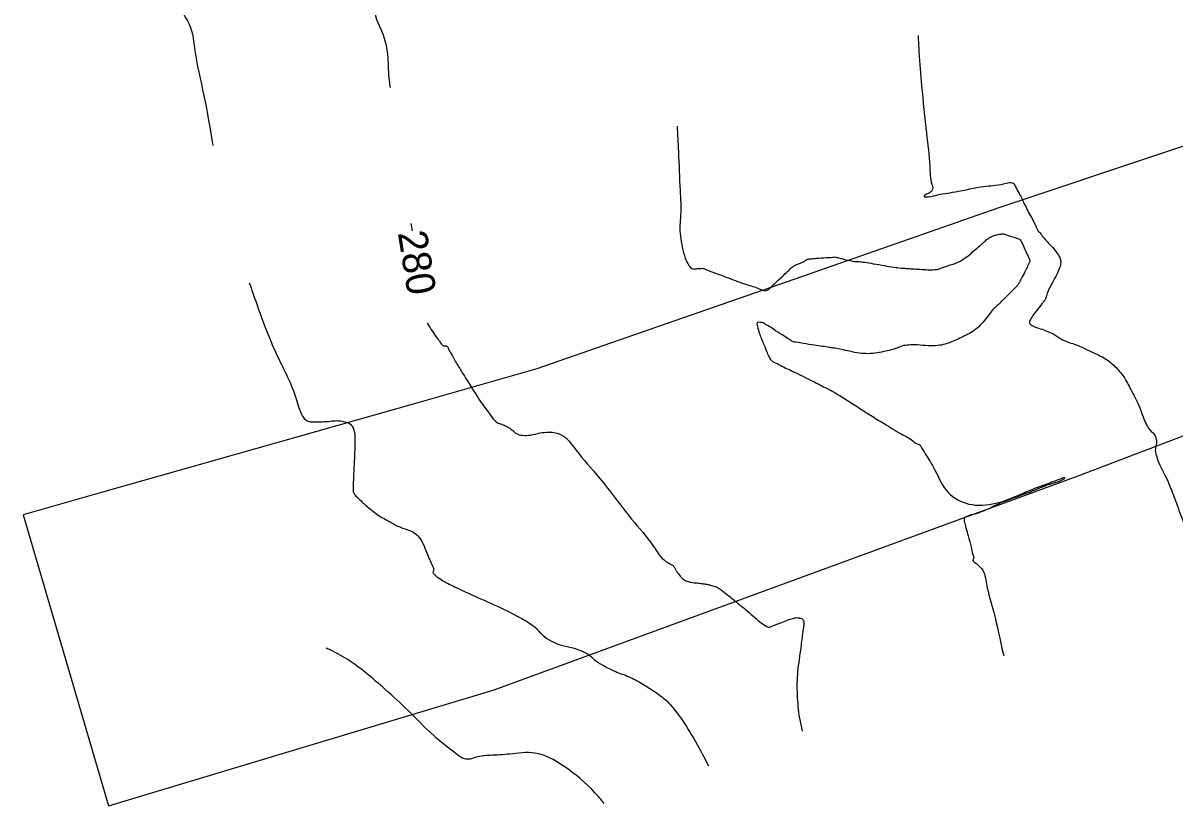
# Model space of a CAD drawing. Extents: x -478645 to -472650, y -1118147 to -1113892.
# Drawn here: x -476249.6 to -476090.4, y -1115350.3 to -1115242.1 of the extents above; entities that cross this region are included whole.
import ezdxf

# ---------------------------------------------------------------- set-up
doc = ezdxf.new("R2010")
doc.units = 0
for name, color, linetype in [('ObPÚ', 7, 'Continuous'), ('Vrstevnice_hlavni', 7, 'Continuous'), ('Vrstevnice_popis', 7, 'Continuous'), ('Vrstevnice_vedlejsi', 7, 'Continuous')]:
    doc.layers.add(name, color=color, linetype=linetype)

msp = doc.modelspace()

# ---------------------------------------------------------------- linework, layer by layer
at = {"layer": 'ObPÚ'}
msp.add_lwpolyline([(-476068.7, -1115252.31), (-476114.88, -1115267.73), (-476138.618, -1115276.003), (-476141.91, -1115277.15), (-476168.45, -1115286.39), (-476178.6, -1115289.93), (-476195.38, -1115294.7), (-476223.04, -1115302.55), (-476238.65, -1115306.98), (-476249.64, -1115310.1), (-476237.84, -1115350.34), (-476184.5, -1115334.29), (-476103.79, -1115304.74), (-476065.34, -1115290.09)], dxfattribs=at)
at = {"layer": 'Vrstevnice_hlavni'}
msp.add_line((-476196.015, -1115269.846), (-476195.861, -1115270.85), dxfattribs=at)
for points in [[(-476040.384, -1115118.458), (-476041.47, -1115119.89), (-476042.412, -1115121.448), (-476043.751, -1115123.849), (-476045.488, -1115127.091), (-476046.696, -1115129.513), (-476047.375, -1115131.113), (-476047.526, -1115131.894), (-476048.073, -1115133.254), (-476049.018, -1115135.194), (-476050.36, -1115137.713), (-476052.374, -1115140.598), (-476055.061, -1115143.847), (-476058.422, -1115147.462), (-476060.881, -1115150.366), (-476062.441, -1115152.562), (-476063.1, -1115154.048), (-476064.028, -1115155.224), (-476065.225, -1115156.09), (-476066.691, -1115156.645), (-476068.203, -1115157.501), (-476069.761, -1115158.657), (-476071.364, -1115160.113), (-476073.585, -1115161.644), (-476076.424, -1115163.251), (-476079.881, -1115164.932), (-476082.243, -1115166.084), (-476083.511, -1115166.709), (-476083.684, -1115166.806), (-476083.884, -1115166.906), (-476084.109, -1115167.009), (-476084.361, -1115167.115), (-476085.47, -1115168.111), (-476087.436, -1115169.998), (-476090.259, -1115172.776), (-476094.056, -1115175.649), (-476098.828, -1115178.618), (-476104.575, -1115181.683), (-476109.757, -1115183.949), (-476114.374, -1115185.417), (-476118.425, -1115186.088), (-476122.042, -1115187.328), (-476125.226, -1115189.137), (-476127.977, -1115191.516), (-476131.019, -1115193.792), (-476134.353, -1115195.963), (-476137.979, -1115198.031), (-476141.984, -1115199.581), (-476146.368, -1115200.612), (-476151.132, -1115201.124), (-476157.864, -1115204.368), (-476166.565, -1115210.343), (-476177.234, -1115219.049), (-476184.652, -1115224.996), (-476188.817, -1115228.184), (-476189.731, -1115228.613), (-476190.168, -1115228.886), (-476190.128, -1115229.002), (-476189.61, -1115228.963), (-476189.269, -1115228.999), (-476189.104, -1115229.11), (-476189.116, -1115229.298), (-476189.143, -1115229.675), (-476189.187, -1115230.241), (-476189.246, -1115230.996), (-476189.162, -1115231.612), (-476188.933, -1115232.089), (-476188.56, -1115232.427), (-476188.448, -1115232.74), (-476188.595, -1115233.026), (-476189.004, -1115233.287), (-476189.464, -1115233.625), (-476189.976, -1115234.04), (-476190.541, -1115234.531), (-476191.953, -1115235.382), (-476194.211, -1115236.59), (-476197.317, -1115238.157), (-476199.41, -1115239.209), (-476200.49, -1115239.748), (-476200.557, -1115239.773), (-476200.072, -1115243.239), (-476199.036, -1115250.148), (-476198.895, -1115251.068)], [(-476193.757, -1115283.639), (-476192.399, -1115285.697), (-476191.876, -1115286.389), (-476191.509, -1115286.744), (-476191.298, -1115286.761), (-476191.153, -1115286.774), (-476191.075, -1115286.783), (-476191.063, -1115286.789), (-476190.853, -1115287.151), (-476190.446, -1115287.871), (-476189.842, -1115288.948), (-476188.923, -1115290.467), (-476187.688, -1115292.429), (-476186.137, -1115294.833), (-476184.891, -1115296.504), (-476183.948, -1115297.443), (-476183.309, -1115297.648), (-476182.68, -1115297.954), (-476182.06, -1115298.362), (-476181.45, -1115298.872), (-476180.595, -1115299.114), (-476179.497, -1115299.088), (-476178.155, -1115298.795), (-476176.997, -1115298.69), (-476176.025, -1115298.773), (-476175.238, -1115299.045), (-476173.224, -1115301.122), (-476169.984, -1115305.003), (-476165.518, -1115310.689), (-476162.449, -1115314.535), (-476160.779, -1115316.54), (-476160.507, -1115316.704), (-476160.264, -1115316.845), (-476160.048, -1115316.962), (-476159.86, -1115317.056), (-476159.707, -1115317.19), (-476159.59, -1115317.365), (-476159.508, -1115317.58), (-476159.311, -1115317.896), (-476158.998, -1115318.315), (-476158.57, -1115318.834), (-476158.007, -1115319.207), (-476157.308, -1115319.433), (-476156.473, -1115319.513), (-476155.76, -1115319.601), (-476155.169, -1115319.698), (-476154.699, -1115319.804), (-476154.303, -1115319.906), (-476153.978, -1115320.004), (-476153.727, -1115320.098), (-476153.145, -1115320.495), (-476152.232, -1115321.193), (-476150.988, -1115322.193), (-476149.831, -1115323.145), (-476148.761, -1115324.046), (-476147.778, -1115324.899), (-476147.017, -1115325.426), (-476146.478, -1115325.629), (-476146.16, -1115325.507), (-476145.635, -1115325.303), (-476144.904, -1115325.017), (-476143.967, -1115324.649), (-476143.233, -1115324.414), (-476142.702, -1115324.312), (-476142.375, -1115324.342), (-476142.123, -1115324.398), (-476141.945, -1115324.481), (-476141.842, -1115324.59), (-476141.767, -1115324.715), (-476141.722, -1115324.858), (-476141.705, -1115325.018), (-476141.842, -1115326.221), (-476142.131, -1115328.466), (-476142.574, -1115331.753), (-476142.636, -1115334.999), (-476142.32, -1115338.203), (-476141.962, -1115339.984)]]:
    msp.add_spline(points, degree=3, dxfattribs=at)
at = {"layer": 'Vrstevnice_vedlejsi'}
for points in [[(-476075.436, -1115157.873), (-476077.562, -1115158.907), (-476079.639, -1115159.964), (-476081.666, -1115161.045), (-476083.644, -1115162.149), (-476085.921, -1115163.289), (-476088.498, -1115164.465), (-476091.373, -1115165.676), (-476093.656, -1115166.843), (-476095.346, -1115167.967), (-476096.444, -1115169.047), (-476097.921, -1115170.165), (-476099.777, -1115171.319), (-476102.012, -1115172.511), (-476105.743, -1115173.677), (-476110.97, -1115174.816), (-476117.692, -1115175.928), (-476122.561, -1115177.005), (-476125.576, -1115178.045), (-476126.738, -1115179.05), (-476129.738, -1115180.989), (-476134.578, -1115183.864), (-476141.257, -1115187.673), (-476147.035, -1115190.356), (-476151.912, -1115191.911), (-476155.888, -1115192.338), (-476158.789, -1115192.754), (-476160.614, -1115193.159), (-476161.364, -1115193.552), (-476162.517, -1115193.939), (-476164.073, -1115194.319), (-476166.032, -1115194.693), (-476167.609, -1115195.158), (-476168.804, -1115195.715), (-476169.616, -1115196.364), (-476170.816, -1115197.116), (-476172.405, -1115197.973), (-476174.383, -1115198.934), (-476179.537, -1115202.555), (-476187.868, -1115208.836), (-476199.377, -1115217.776), (-476207.75, -1115223.932), (-476212.989, -1115227.302), (-476215.093, -1115227.888), (-476217.31, -1115229.046), (-476219.639, -1115230.776), (-476222.081, -1115233.079), (-476224.102, -1115235.091), (-476225.704, -1115236.812), (-476226.884, -1115238.243), (-476227.475, -1115239.561), (-476227.475, -1115240.767), (-476226.885, -1115241.861), (-476225.939, -1115245.662), (-476224.639, -1115252.17), (-476223.41, -1115259.087)], [(-476125.929, -1115243.884), (-476125.807, -1115246.158), (-476125.427, -1115250.782), (-476124.774, -1115257.383), (-476124.301, -1115261.931), (-476124.008, -1115264.426), (-476123.894, -1115264.868), (-476123.981, -1115265.246), (-476124.269, -1115265.56), (-476124.757, -1115265.811), (-476125.029, -1115265.996), (-476125.083, -1115266.115), (-476124.92, -1115266.169), (-476123.491, -1115265.956), (-476120.797, -1115265.476), (-476116.836, -1115264.728), (-476114.123, -1115264.363), (-476112.657, -1115264.382), (-476112.438, -1115264.783), (-476111.966, -1115265.692), (-476111.241, -1115267.111), (-476110.263, -1115269.038), (-476109.58, -1115270.343), (-476109.193, -1115271.027), (-476109.102, -1115271.089), (-476109.038, -1115271.136), (-476109.003, -1115271.169), (-476108.995, -1115271.186), (-476108.962, -1115271.248), (-476108.904, -1115271.357), (-476108.821, -1115271.512), (-476108.502, -1115271.894), (-476107.946, -1115272.505), (-476107.155, -1115273.343), (-476106.601, -1115274.081), (-476106.285, -1115274.719), (-476106.206, -1115275.258), (-476106.359, -1115275.986), (-476106.744, -1115276.905)], [(-476159.242, -1115256.374), (-476159.054, -1115259.908), (-476158.82, -1115265.295), (-476158.75, -1115268.706), (-476158.845, -1115270.139), (-476158.769, -1115271.604), (-476158.523, -1115273.101), (-476158.106, -1115274.629), (-476157.613, -1115275.635), (-476157.044, -1115276.119), (-476156.398, -1115276.081), (-476155.961, -1115276.055), (-476155.733, -1115276.04), (-476155.713, -1115276.036), (-476155.581, -1115276.081), (-476155.338, -1115276.173), (-476154.983, -1115276.314), (-476153.911, -1115276.714), (-476152.122, -1115277.373), (-476149.617, -1115278.29), (-476147.877, -1115278.87), (-476146.903, -1115279.111), (-476146.694, -1115279.015), (-476146.533, -1115278.92), (-476146.42, -1115278.827), (-476146.354, -1115278.736), (-476146.034, -1115278.42), (-476145.458, -1115277.878), (-476144.627, -1115277.111), (-476144.009, -1115276.53), (-476143.606, -1115276.135), (-476143.416, -1115275.928), (-476143.115, -1115275.721), (-476142.7, -1115275.515), (-476142.174, -1115275.31), (-476141.777, -1115275.132), (-476141.512, -1115274.98), (-476141.376, -1115274.855), (-476140.853, -1115274.744), (-476139.943, -1115274.647), (-476138.645, -1115274.565), (-476137.773, -1115274.512), (-476137.326, -1115274.488), (-476137.304, -1115274.493), (-476137.022, -1115274.564), (-476136.479, -1115274.699), (-476135.676, -1115274.9), (-476135.01, -1115275.037), (-476134.48, -1115275.109), (-476134.087, -1115275.117), (-476133.301, -1115275.213), (-476132.123, -1115275.399), (-476130.553, -1115275.673), (-476129.267, -1115275.873), (-476128.264, -1115275.998), (-476127.545, -1115276.049), (-476126.691, -1115276.105), (-476125.702, -1115276.169), (-476124.578, -1115276.238), (-476123.673, -1115276.222), (-476122.988, -1115276.122), (-476122.522, -1115275.938), (-476121.968, -1115275.735), (-476121.325, -1115275.516), (-476120.594, -1115275.279), (-476119.818, -1115274.872), (-476118.996, -1115274.295), (-476118.13, -1115273.548), (-476117.407, -1115272.922), (-476116.827, -1115272.417), (-476116.391, -1115272.033), (-476115.924, -1115271.733), (-476115.425, -1115271.516), (-476114.896, -1115271.383), (-476114.504, -1115271.301), (-476114.247, -1115271.269), (-476114.127, -1115271.287), (-476113.822, -1115271.374), (-476113.331, -1115271.529), (-476112.656, -1115271.752), (-476112.177, -1115271.921), (-476111.894, -1115272.035), (-476111.807, -1115272.094), (-476111.623, -1115272.416), (-476111.341, -1115273)], [(-476111.341, -1115273), (-476110.962, -1115273.848), (-476110.694, -1115274.441), (-476110.537, -1115274.78), (-476110.491, -1115274.865), (-476110.47, -1115274.959), (-476110.475, -1115275.062), (-476110.506, -1115275.174), (-476110.69, -1115275.573), (-476111.03, -1115276.26), (-476111.524, -1115277.233), (-476111.877, -1115277.912), (-476112.088, -1115278.296), (-476112.158, -1115278.386), (-476112.514, -1115278.752), (-476113.156, -1115279.397), (-476114.085, -1115280.319), (-476114.761, -1115280.979), (-476115.186, -1115281.379), (-476115.36, -1115281.517), (-476115.713, -1115281.919), (-476116.247, -1115282.585), (-476116.962, -1115283.514), (-476117.741, -1115284.291), (-476118.584, -1115284.915), (-476119.493, -1115285.387), (-476120.392, -1115285.812), (-476121.284, -1115286.191), (-476122.167, -1115286.523), (-476123.251, -1115286.707), (-476124.536, -1115286.741), (-476126.022, -1115286.628), (-476127.231, -1115286.643), (-476128.162, -1115286.786), (-476128.816, -1115287.059), (-476129.654, -1115287.316), (-476130.678, -1115287.555), (-476131.887, -1115287.779), (-476133.124, -1115287.833), (-476134.388, -1115287.719), (-476135.68, -1115287.435), (-476136.751, -1115287.215), (-476137.602, -1115287.058), (-476138.232, -1115286.963), (-476139.134, -1115286.827), (-476140.308, -1115286.649), (-476141.754, -1115286.429), (-476142.752, -1115286.26), (-476143.303, -1115286.142), (-476143.406, -1115286.075), (-476143.876, -1115285.775), (-476144.711, -1115285.24), (-476145.912, -1115284.47), (-476146.719, -1115283.95), (-476147.131, -1115283.678), (-476147.149, -1115283.654), (-476147.194, -1115283.626), (-476147.267, -1115283.594), (-476147.366, -1115283.557), (-476147.542, -1115283.533), (-476147.795, -1115283.522), (-476148.124, -1115283.524), (-476148.141, -1115284.035), (-476147.848, -1115285.056), (-476147.243, -1115286.586), (-476146.785, -1115287.691), (-476146.474, -1115288.372), (-476146.31, -1115288.628), (-476146.156, -1115288.817), (-476146.012, -1115288.938), (-476145.878, -1115288.992), (-476144.948, -1115289.442), (-476143.224, -1115290.289), (-476140.705, -1115291.532), (-476138.75, -1115292.524), (-476137.361, -1115293.265), (-476136.537, -1115293.756), (-476135.685, -1115294.285), (-476134.806, -1115294.853), (-476133.899, -1115295.46), (-476132.503, -1115296.342), (-476130.618, -1115297.498), (-476128.243, -1115298.929), (-476126.641, -1115299.885), (-476125.811, -1115300.366), (-476125.755, -1115300.372), (-476125.7, -1115300.405), (-476125.646, -1115300.464), (-476125.594, -1115300.551), (-476124.922, -1115301.679), (-476123.631, -1115303.848), (-476121.721, -1115307.059), (-476118.902, -1115308.612), (-476115.176, -1115308.508), (-476110.541, -1115306.747), (-476107.432, -1115305.567), (-476105.848, -1115304.97)], [(-476218.376, -1115278.038), (-476217.875, -1115279.456), (-476214.425, -1115288.313), (-476211.835, -1115294.229), (-476210.106, -1115297.205), (-476209.237, -1115297.241), (-476208.349, -1115297.236), (-476207.441, -1115297.189), (-476206.512, -1115297.099), (-476205.696, -1115297.136), (-476204.991, -1115297.297), (-476204.399, -1115297.584), (-476203.999, -1115298.149), (-476203.792, -1115298.991), (-476203.779, -1115300.111), (-476203.805, -1115301.478), (-476203.871, -1115303.093), (-476203.978, -1115304.956), (-476204.004, -1115306.275), (-476203.949, -1115307.051), (-476203.815, -1115307.284), (-476203.415, -1115307.714), (-476202.75, -1115308.342), (-476201.819, -1115309.168), (-476200.943, -1115309.859), (-476200.122, -1115310.415), (-476199.355, -1115310.837), (-476198.758, -1115311.169), (-476198.331, -1115311.411), (-476198.073, -1115311.564), (-476197.577, -1115311.782), (-476196.841, -1115312.065), (-476195.867, -1115312.414), (-476195.041, -1115313.077), (-476194.362, -1115314.054), (-476193.831, -1115315.346), (-476193.423, -1115316.323), (-476193.136, -1115316.986), (-476192.972, -1115317.333), (-476192.894, -1115317.625), (-476192.903, -1115317.861)], [(-476106.744, -1115276.905), (-476107.361, -1115278.014), (-476107.805, -1115278.877), (-476108.078, -1115279.493), (-476108.177, -1115279.862), (-476108.25, -1115280.122), (-476108.297, -1115280.271), (-476108.317, -1115280.311), (-476108.573, -1115280.647), (-476109.065, -1115281.28), (-476109.793, -1115282.209), (-476110.279, -1115282.913), (-476110.525, -1115283.392), (-476110.528, -1115283.645), (-476110.197, -1115283.923), (-476109.532, -1115284.226), (-476108.532, -1115284.553), (-476107.69, -1115284.894), (-476107.005, -1115285.251), (-476106.478, -1115285.622), (-476105.861, -1115285.956), (-476105.153, -1115286.251), (-476104.354, -1115286.507), (-476103.257, -1115286.96), (-476101.863, -1115287.61), (-476100.172, -1115288.455), (-476098.717, -1115289.598), (-476097.498, -1115291.039), (-476096.516, -1115292.777), (-476095.725, -1115294.323), (-476095.126, -1115295.678), (-476094.718, -1115296.841), (-476094.281, -1115297.767), (-476093.815, -1115298.456), (-476093.319, -1115298.907), (-476093.04, -1115299.473), (-476092.976, -1115300.153), (-476093.128, -1115300.947), (-476092.975, -1115301.971), (-476092.517, -1115303.223), (-476091.755, -1115304.704), (-476090.913, -1115306.661), (-476089.99, -1115309.094), (-476088.988, -1115312.004), (-476088.293, -1115314.278), (-476087.906, -1115315.919), (-476087.826, -1115316.925), (-476087.506, -1115318.414), (-476087.193, -1115319.54)], [(-476105.848, -1115304.97), (-476105.79, -1115304.953), (-476105.742, -1115304.95), (-476105.706, -1115304.96), (-476105.681, -1115304.983), (-476105.665, -1115305.007), (-476105.66, -1115305.032), (-476105.665, -1115305.057), (-476105.684, -1115305.087), (-476105.717, -1115305.122), (-476105.765, -1115305.16), (-476107.334, -1115305.771), (-476110.427, -1115306.953), (-476115.042, -1115308.707), (-476118.091, -1115309.993), (-476119.575, -1115310.812), (-476119.492, -1115311.162), (-476119.302, -1115311.898), (-476119.003, -1115313.019), (-476118.597, -1115314.525), (-476118.349, -1115315.58), (-476118.261, -1115316.183), (-476118.333, -1115316.335), (-476118.325, -1115316.469), (-476118.238, -1115316.585), (-476118.073, -1115316.683), (-476117.836, -1115316.872), (-476117.529, -1115317.152), (-476117.151, -1115317.523), (-476116.463, -1115319.666), (-476115.466, -1115323.582), (-476114.16, -1115329.271), (-476114.085, -1115329.578)], [(-476192.903, -1115317.861), (-476192.999, -1115318.042), (-476192.816, -1115318.327), (-476192.354, -1115318.716), (-476191.613, -1115319.21), (-476189.891, -1115320.089), (-476187.188, -1115321.354), (-476183.505, -1115323.005), (-476180.713, -1115324.453), (-476178.814, -1115325.697), (-476177.806, -1115326.737), (-476176.612, -1115327.549), (-476175.23, -1115328.132), (-476173.662, -1115328.486), (-476172.346, -1115328.961), (-476171.282, -1115329.555), (-476170.47, -1115330.27), (-476169.305, -1115330.996), (-476167.786, -1115331.732), (-476165.913, -1115332.48), (-476164.102, -1115333.412), (-476162.353, -1115334.527), (-476160.666, -1115335.826), (-476158.775, -1115338.132), (-476156.681, -1115341.444), (-476154.893, -1115344.811)], [(-476169.317, -1115349.984), (-476170.582, -1115348.511), (-476174.959, -1115344.81), (-476178.893, -1115343.028), (-476182.384, -1115343.164), (-476185.085, -1115343.353), (-476186.997, -1115343.594), (-476188.119, -1115343.887), (-476190.063, -1115342.911), (-476192.828, -1115340.664), (-476196.414, -1115337.147), (-476199.562, -1115334.239), (-476202.271, -1115331.942), (-476204.542, -1115330.254), (-476207.149, -1115328.799), (-476207.747, -1115328.526)]]:
    msp.add_spline(points, degree=3, dxfattribs=at)

# ---------------------------------------------------------------- texts
at = {"layer": 'Vrstevnice_popis'}
msp.add_text(' 280 ', height=4, rotation=279.08544, dxfattribs=at).set_placement((-476198.078, -1115269.663))

doc.saveas('drawing.dxf')
